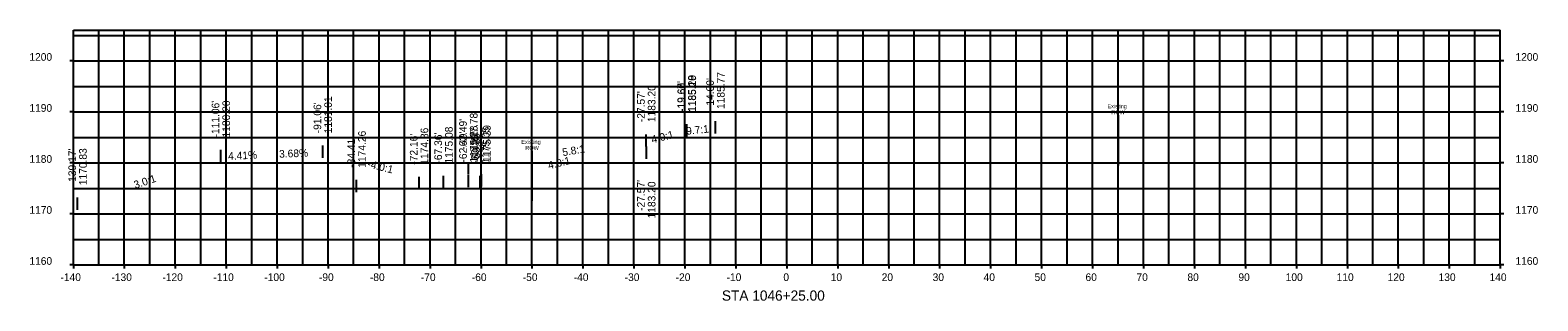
# Model space of a CAD drawing. Extents: x -148 to 147, y 1153 to 1206.
import ezdxf

# ---------------------------------------------------------------- set-up
doc = ezdxf.new("R2010")
doc.units = 0
for name, color, linetype in [('Contours Major', 7, 'Continuous'), ('Contours Minor', 7, 'Continuous'), ('Draft_1', 7, 'Continuous'), ('Draft_4', 7, 'Continuous'), ('Draft_7', 7, 'Continuous'), ('Draft_8', 7, 'Continuous')]:
    doc.layers.add(name, color=color, linetype=linetype)

msp = doc.modelspace()

# ---------------------------------------------------------------- linework, layer by layer
at = {"layer": 'Contours Major'}
for p, q in [((-19.67, 1185.18), (-19.67, 1187.58)), ((-19.66, 1185.2), (-19.66, 1187.6)), ((-19.6, 1185.19), (-19.6, 1187.59)), ((-19.6, 1185.19), (-19.6, 1187.59)), ((-14, 1185.77), (-14, 1188.17)), ((-27.57, 1183.2), (-27.57, 1185.6)), ((-111.06, 1180.2), (-111.06, 1182.6)), ((-91.06, 1181.01), (-91.06, 1183.41)), ((-27.57, 1183.2), (-27.57, 1180.8)), ((-62.49, 1177.78), (-62.49, 1180.18)), ((-62.49, 1175.28), (-62.49, 1177.68)), ((-59.89, 1175.39), (-59.89, 1177.79)), ((-84.41, 1174.26), (-84.41, 1176.66)), ((-72.16, 1174.86), (-72.16, 1177.26)), ((-67.36, 1175.08), (-67.36, 1177.48)), ((-60.15, 1175.05), (-60.15, 1177.45)), ((-139.17, 1170.83), (-139.17, 1173.23))]:
    msp.add_line(p, q, dxfattribs=at)
at = {"layer": 'Draft_1'}
for p, q in [((-140, 1205), (140, 1205)), ((-135, 1160), (-135, 1206.03)), ((-125, 1160), (-125, 1206.03)), ((-115, 1160), (-115, 1206.03)), ((-105, 1160), (-105, 1206.03)), ((-95, 1160), (-95, 1206.03)), ((-85, 1160), (-85, 1206.03)), ((-75, 1160), (-75, 1206.03)), ((-65, 1160), (-65, 1206.03)), ((-55, 1160), (-55, 1206.03)), ((-45, 1160), (-45, 1206.03)), ((-35, 1160), (-35, 1206.03)), ((-25, 1160), (-25, 1206.03)), ((-15, 1160), (-15, 1206.03)), ((-5, 1160), (-5, 1206.03)), ((5, 1160), (5, 1206.03)), ((15, 1160), (15, 1206.03)), ((25, 1160), (25, 1206.03)), ((35, 1160), (35, 1206.03)), ((45, 1160), (45, 1206.03)), ((55, 1160), (55, 1206.03)), ((65, 1160), (65, 1206.03)), ((75, 1160), (75, 1206.03)), ((85, 1160), (85, 1206.03)), ((95, 1160), (95, 1206.03)), ((105, 1160), (105, 1206.03)), ((115, 1160), (115, 1206.03)), ((125, 1160), (125, 1206.03)), ((135, 1160), (135, 1206.03)), ((-140, 1195), (140, 1195)), ((-140, 1185), (140, 1185)), ((-140, 1175), (140, 1175)), ((-140, 1165), (140, 1165))]:
    msp.add_line(p, q, dxfattribs=at)
at = {"layer": 'Draft_4'}
for p, q in [((-140, 1206.03), (140, 1206.03)), ((-140, 1160), (-140, 1206.03)), ((140, 1160), (140, 1206.03)), ((-140, 1160), (140, 1160))]:
    msp.add_line(p, q, dxfattribs=at)
at = {"layer": 'Draft_7'}
for p, q in [((65.01, 1189.38), (65.01, 1179.53)), ((-50, 1182.39), (-50, 1172.54))]:
    msp.add_line(p, q, dxfattribs=at)
at = {"layer": 'Draft_8'}
for p, q in [((-130, 1160), (-130, 1206.03)), ((-120, 1160), (-120, 1206.03)), ((-110, 1160), (-110, 1206.03)), ((-100, 1160), (-100, 1206.03)), ((-90, 1160), (-90, 1206.03)), ((-80, 1160), (-80, 1206.03)), ((-70, 1160), (-70, 1206.03)), ((-60, 1160), (-60, 1206.03)), ((-50, 1160), (-50, 1206.03)), ((-40, 1160), (-40, 1206.03)), ((-30, 1160), (-30, 1206.03)), ((-20, 1160), (-20, 1206.03)), ((-10, 1160), (-10, 1206.03)), ((0, 1160), (0, 1206.03)), ((10, 1160), (10, 1206.03)), ((20, 1160), (20, 1206.03)), ((30, 1160), (30, 1206.03)), ((40, 1160), (40, 1206.03)), ((50, 1160), (50, 1206.03)), ((60, 1160), (60, 1206.03)), ((70, 1160), (70, 1206.03)), ((80, 1160), (80, 1206.03)), ((90, 1160), (90, 1206.03)), ((100, 1160), (100, 1206.03)), ((110, 1160), (110, 1206.03)), ((120, 1160), (120, 1206.03)), ((130, 1160), (130, 1206.03)), ((-140, 1200), (-140.72, 1200)), ((-140, 1200), (140, 1200)), ((140.72, 1200), (140, 1200)), ((-140, 1190), (-140.72, 1190)), ((-140, 1190), (140, 1190)), ((140.72, 1190), (140, 1190)), ((-140, 1180), (-140.72, 1180)), ((-140, 1180), (140, 1180)), ((140.72, 1180), (140, 1180)), ((-140, 1170), (-140.72, 1170)), ((-140, 1170), (140, 1170)), ((140.72, 1170), (140, 1170)), ((-140, 1160), (-140.72, 1160)), ((-140, 1160), (-140, 1159.28)), ((-130, 1160), (-130, 1159.28)), ((-120, 1160), (-120, 1159.28)), ((-110, 1160), (-110, 1159.28)), ((-100, 1160), (-100, 1159.28)), ((-90, 1160), (-90, 1159.28)), ((-80, 1160), (-80, 1159.28)), ((-70, 1160), (-70, 1159.28)), ((-60, 1160), (-60, 1159.28)), ((-50, 1160), (-50, 1159.28)), ((-40, 1160), (-40, 1159.28)), ((-30, 1160), (-30, 1159.28)), ((-20, 1160), (-20, 1159.28)), ((-10, 1160), (-10, 1159.28)), ((0, 1160), (0, 1159.28)), ((10, 1160), (10, 1159.28)), ((20, 1160), (20, 1159.28)), ((30, 1160), (30, 1159.28)), ((40, 1160), (40, 1159.28)), ((50, 1160), (50, 1159.28)), ((60, 1160), (60, 1159.28)), ((70, 1160), (70, 1159.28)), ((80, 1160), (80, 1159.28)), ((90, 1160), (90, 1159.28)), ((100, 1160), (100, 1159.28)), ((110, 1160), (110, 1159.28)), ((120, 1160), (120, 1159.28)), ((130, 1160), (130, 1159.28)), ((140, 1160), (140, 1159.28)), ((140.72, 1160), (140, 1160))]:
    msp.add_line(p, q, dxfattribs=at)

# ---------------------------------------------------------------- texts
at = {"layer": 'Contours Major'}
for s, rotation, p in [("-19.67'", 90, (-19.97, 1189.98)), ("-19.66'", 90, (-19.96, 1190)), ("-19.60'", 90, (-19.9, 1189.99)), ("-19.60'", 90, (-19.9, 1189.99)), ('1185.18', 90, (-17.87, 1189.98)), ('1185.20', 90, (-17.86, 1190)), ('1185.19', 90, (-17.8, 1189.99)), ('1185.19', 90, (-17.8, 1189.99)), ("-14.00'", 90, (-14.3, 1190.57)), ('1185.77', 90, (-12.2, 1190.57)), ('1181.01', 90, (-89.26, 1185.81)), ("-27.57'", 90, (-27.87, 1188)), ('1183.20', 90, (-25.77, 1188)), ("-111.06'", 90, (-111.36, 1185)), ('1180.20', 90, (-109.26, 1185)), ("-91.06'", 90, (-91.36, 1185.81)), ('1177.78', 90, (-60.69, 1182.58)), ('1174.86', 90, (-70.36, 1179.66)), ('1175.08', 90, (-65.56, 1179.88)), ("-62.49'", 90, (-62.79, 1182.58)), ('1175.28', 90, (-60.69, 1180.08)), ('1175.05', 90, (-58.35, 1179.85)), ('1175.39', 90, (-58.09, 1180.19)), ('9.7:1', 5.902, (-19.67, 1185.51)), ("-84.41'", 90, (-84.71, 1179.06)), ('1174.26', 90, (-82.61, 1179.06)), ("-72.16'", 90, (-72.46, 1179.66)), ("-67.36'", 90, (-67.66, 1179.88)), ("-62.49'", 90, (-62.79, 1180.08)), ("-60.15'", 90, (-60.45, 1179.85)), ("-59.89'", 90, (-60.19, 1180.19)), ('5.8:1', 9.7927, (-43.92, 1181.32)), ('4.0:1', 14.0362, (-26.38, 1183.83)), ("-139.17'", 90, (-139.47, 1175.63)), ('1170.83', 90, (-137.37, 1175.63)), ('4.41%', 2.526, (-109.6, 1180.59)), ('3.68%', 2.1091, (-99.6, 1181.02)), ('4.0:1', 14.0362, (-46.66, 1178.76)), ('3.0:1', 18.43, (-127.86, 1174.93)), ('-4.0:1', 345.9584, (-82.41, 1179.17)), ("-27.57'", 90, (-27.87, 1170.6)), ('1183.20', 90, (-25.77, 1169.12))]:
    msp.add_text(s, height=1.5, rotation=rotation, dxfattribs=at).set_placement(p)
at = {"layer": 'Contours Minor'}
for s, height, p in [('1200', 1.5, (-148.63, 1200.03)), ('1200', 1.5, (143, 1200.03)), ('1190', 1.5, (-148.63, 1190.03)), ('1190', 1.5, (143, 1190.03)), ('1180', 1.5, (-148.63, 1180.03)), ('1180', 1.5, (143, 1180.03)), ('1170', 1.5, (-148.63, 1170.03)), ('1170', 1.5, (143, 1170.03)), ('1160', 1.5, (-148.63, 1160.03)), ('1160', 1.5, (143, 1160.03)), ('-140', 1.5, (-142.53, 1156.85)), ('-130', 1.5, (-132.53, 1156.85)), ('-120', 1.5, (-122.53, 1156.85)), ('-110', 1.5, (-112.53, 1156.85)), ('-100', 1.5, (-102.53, 1156.85)), ('-90', 1.5, (-91.81, 1156.85)), ('-80', 1.5, (-81.81, 1156.85)), ('-70', 1.5, (-71.81, 1156.85)), ('-60', 1.5, (-61.81, 1156.85)), ('-50', 1.5, (-51.81, 1156.85)), ('-40', 1.5, (-41.81, 1156.85)), ('-30', 1.5, (-31.81, 1156.85)), ('-20', 1.5, (-21.81, 1156.85)), ('-10', 1.5, (-11.81, 1156.85)), ('0', 1.5, (-0.67, 1156.85)), ('10', 1.5, (8.62, 1156.85)), ('20', 1.5, (18.62, 1156.85)), ('30', 1.5, (28.62, 1156.85)), ('40', 1.5, (38.62, 1156.85)), ('50', 1.5, (48.62, 1156.85)), ('60', 1.5, (58.62, 1156.85)), ('70', 1.5, (68.62, 1156.85)), ('80', 1.5, (78.62, 1156.85)), ('90', 1.5, (88.62, 1156.85)), ('100', 1.5, (97.9, 1156.85)), ('110', 1.5, (107.9, 1156.85)), ('120', 1.5, (117.9, 1156.85)), ('130', 1.5, (127.9, 1156.85)), ('140', 1.5, (137.9, 1156.85)), ('STA 1046+25.00', 2.004, (-12.73, 1153))]:
    msp.add_text(s, height=height, dxfattribs=at).set_placement(p)
at = {"layer": 'Draft_7'}
for s, p in [('Existing', (62.92, 1190.73)), ('ROW', (63.69, 1189.55)), ('Existing', (-52.09, 1183.74)), ('ROW', (-51.31, 1182.56))]:
    msp.add_text(s, height=0.787, dxfattribs=at).set_placement(p)

doc.saveas('drawing.dxf')
